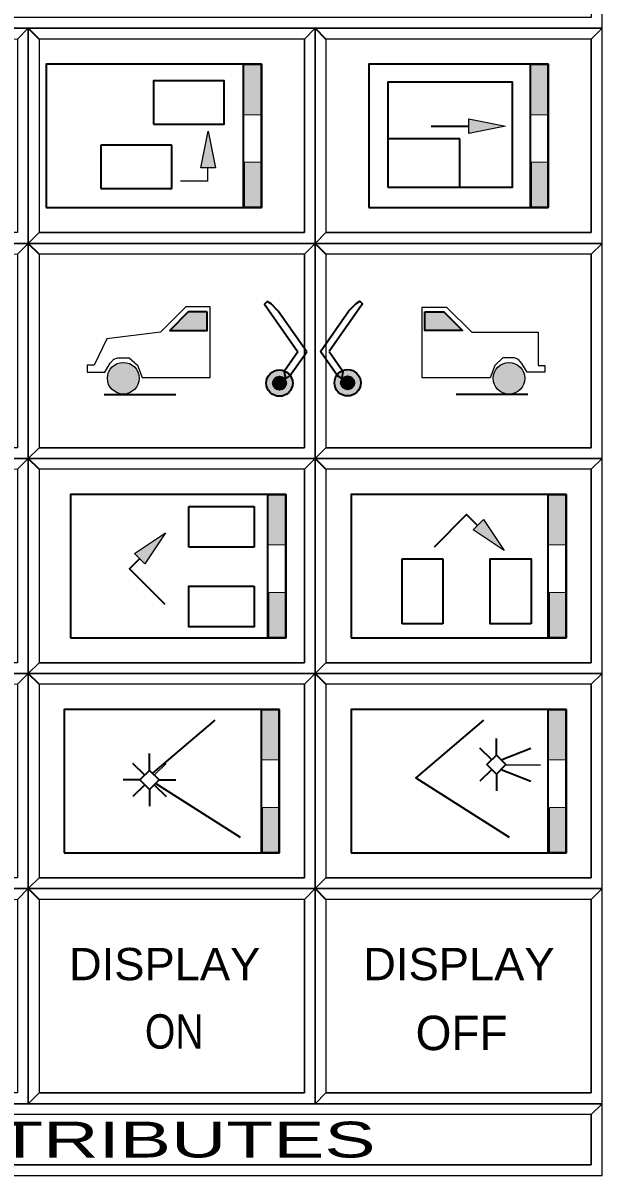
# Model space of a CAD drawing. Extents: x 95906.9 to 95918.9, y 90964.8 to 90972.9.
# Drawn here: x 95917.125 to 95917.932, y 90966.369 to 90967.969 of the extents above; entities that cross this region are included whole.
import ezdxf
from ezdxf.enums import TextEntityAlignment as Align

# ---------------------------------------------------------------- set-up
doc = ezdxf.new("R2010")
doc.units = 0
doc.header["$LTSCALE"] = 0.019
doc.linetypes.add('MEDIUM_DASHED', pattern=[4.5, 3, -1.5])
for name, color, linetype, lineweight in [('1', 7, 'Continuous', 25), ('11', 7, 'Continuous', 25), ('2', 7, 'Continuous', 13), ('21', 7, 'Continuous', 25), ('3', 7, 'Continuous', 25), ('4', 7, 'Continuous', 35), ('6', 7, 'Continuous', 35)]:
    doc.layers.add(name, color=color, linetype=linetype, lineweight=lineweight)

msp = doc.modelspace()

# ---------------------------------------------------------------- hatches: boundary and pattern name
at = {"layer": '6'}
for points in [[(95917.4573, 90967.9117), (95917.4315, 90967.9117), (95917.4315, 90967.8412), (95917.4573, 90967.8412)], [(95917.8573, 90967.9117), (95917.8315, 90967.9117), (95917.8315, 90967.8412), (95917.8573, 90967.8412)], [(95917.7465, 90967.8354), (95917.7977, 90967.8252), (95917.7465, 90967.815)], [(95917.373, 90967.7669), (95917.3832, 90967.8181), (95917.3934, 90967.7669)], [(95917.4339, 90967.7117), (95917.4573, 90967.7117), (95917.4573, 90967.775), (95917.4339, 90967.775)], [(95917.8339, 90967.7117), (95917.8573, 90967.7117), (95917.8573, 90967.775), (95917.8339, 90967.775)], [(95917.3819, 90967.5664), (95917.3554, 90967.5664), (95917.3294, 90967.5404), (95917.3819, 90967.5404)], [(95917.6853, 90967.5662), (95917.7118, 90967.5662), (95917.7378, 90967.5402), (95917.6853, 90967.5402)], [(95917.2426, 90967.4737, 1), (95917.2867, 90967.4737, 1)], [(95917.8246, 90967.4735, 1), (95917.7805, 90967.4735, 1)], [(95917.5009, 90967.4668, 1), (95917.4641, 90967.4668, 1)], [(95917.4917, 90967.4668, 1), (95917.4733, 90967.4668, 1)], [(95917.5591, 90967.4673, 1), (95917.5959, 90967.4673, 1)], [(95917.5683, 90967.4673, 1), (95917.5867, 90967.4673, 1)], [(95917.4912, 90967.3117), (95917.4654, 90967.3117), (95917.4654, 90967.2412), (95917.4912, 90967.2412)], [(95917.8823, 90967.3117), (95917.8565, 90967.3117), (95917.8565, 90967.2412), (95917.8823, 90967.2412)], [(95917.7668, 90967.2768), (95917.7958, 90967.2334), (95917.7524, 90967.2624)], [(95917.2803, 90967.229), (95917.3237, 90967.258), (95917.2947, 90967.2146)], [(95917.4678, 90967.1117), (95917.4912, 90967.1117), (95917.4912, 90967.175), (95917.4678, 90967.175)], [(95917.8589, 90967.1117), (95917.8823, 90967.1117), (95917.8823, 90967.175), (95917.8589, 90967.175)], [(95917.4823, 90967.0117), (95917.4565, 90967.0117), (95917.4565, 90966.9412), (95917.4823, 90966.9412)], [(95917.8823, 90967.0117), (95917.8565, 90967.0117), (95917.8565, 90966.9412), (95917.8823, 90966.9412)], [(95917.4589, 90966.8117), (95917.4823, 90966.8117), (95917.4823, 90966.875), (95917.4589, 90966.875)], [(95917.8589, 90966.8117), (95917.8823, 90966.8117), (95917.8823, 90966.875), (95917.8589, 90966.875)]]:
    msp.add_hatch(color=256, dxfattribs=at).paths.add_polyline_path(points)

# ---------------------------------------------------------------- linework, layer by layer
at = {"layer": '1'}
for points in [[(95916.3323, 90967.9617), (95917.9323, 90967.9617), (95917.9323, 90968.0617), (95916.3323, 90968.0617)], [(95916.7323, 90967.6617), (95917.1323, 90967.6617), (95917.1323, 90967.9617), (95916.7323, 90967.9617)], [(95917.1323, 90967.6617), (95917.5323, 90967.6617), (95917.5323, 90967.9617), (95917.1323, 90967.9617)], [(95917.5323, 90967.6617), (95917.9323, 90967.6617), (95917.9323, 90967.9617), (95917.5323, 90967.9617)], [(95916.7323, 90967.3617), (95917.1323, 90967.3617), (95917.1323, 90967.6617), (95916.7323, 90967.6617)], [(95917.1323, 90967.3617), (95917.5323, 90967.3617), (95917.5323, 90967.6617), (95917.1323, 90967.6617)], [(95917.5323, 90967.3617), (95917.9323, 90967.3617), (95917.9323, 90967.6617), (95917.5323, 90967.6617)], [(95916.7323, 90967.0617), (95917.1323, 90967.0617), (95917.1323, 90967.3617), (95916.7323, 90967.3617)], [(95917.1323, 90967.0617), (95917.5323, 90967.0617), (95917.5323, 90967.3617), (95917.1323, 90967.3617)], [(95917.5323, 90967.0617), (95917.9323, 90967.0617), (95917.9323, 90967.3617), (95917.5323, 90967.3617)], [(95916.7323, 90966.7617), (95917.1323, 90966.7617), (95917.1323, 90967.0617), (95916.7323, 90967.0617)], [(95917.1323, 90966.7617), (95917.5323, 90966.7617), (95917.5323, 90967.0617), (95917.1323, 90967.0617)], [(95917.5323, 90966.7617), (95917.9323, 90966.7617), (95917.9323, 90967.0617), (95917.5323, 90967.0617)], [(95916.7323, 90966.4617), (95917.1323, 90966.4617), (95917.1323, 90966.7617), (95916.7323, 90966.7617)], [(95917.1323, 90966.4617), (95917.5323, 90966.4617), (95917.5323, 90966.7617), (95917.1323, 90966.7617)], [(95917.5323, 90966.4617), (95917.9323, 90966.4617), (95917.9323, 90966.7617), (95917.5323, 90966.7617)], [(95916.3323, 90966.3617), (95917.9323, 90966.3617), (95917.9323, 90966.4617), (95916.3323, 90966.4617)]]:
    msp.add_lwpolyline(points, close=True, dxfattribs=at)
at = {"layer": '11'}
for points in [[(95917.1473, 90967.6767), (95917.5173, 90967.6767), (95917.5173, 90967.9467), (95917.1473, 90967.9467)], [(95917.5473, 90967.6767), (95917.9173, 90967.6767), (95917.9173, 90967.9467), (95917.5473, 90967.9467)], [(95917.1473, 90967.3767), (95917.5173, 90967.3767), (95917.5173, 90967.6467), (95917.1473, 90967.6467)], [(95917.5473, 90967.3767), (95917.9173, 90967.3767), (95917.9173, 90967.6467), (95917.5473, 90967.6467)], [(95917.1473, 90967.0767), (95917.5173, 90967.0767), (95917.5173, 90967.3467), (95917.1473, 90967.3467)], [(95917.5473, 90967.0767), (95917.9173, 90967.0767), (95917.9173, 90967.3467), (95917.5473, 90967.3467)], [(95917.1473, 90966.7767), (95917.5173, 90966.7767), (95917.5173, 90967.0467), (95917.1473, 90967.0467)], [(95917.5473, 90966.7767), (95917.9173, 90966.7767), (95917.9173, 90967.0467), (95917.5473, 90967.0467)], [(95917.1473, 90966.4767), (95917.5173, 90966.4767), (95917.5173, 90966.7467), (95917.1473, 90966.7467)], [(95917.5473, 90966.4767), (95917.9173, 90966.4767), (95917.9173, 90966.7467), (95917.5473, 90966.7467)]]:
    msp.add_lwpolyline(points, close=True, dxfattribs=at)
at = {"layer": '2'}
for points in [[(95916.7323, 90967.9617), (95916.7323, 90967.6617), (95916.7473, 90967.6767), (95916.7473, 90967.9467), (95917.1173, 90967.9467), (95917.1323, 90967.9617)], [(95917.1323, 90967.9617), (95917.1323, 90967.6617), (95917.1473, 90967.6767), (95917.1473, 90967.9467), (95917.5173, 90967.9467), (95917.5323, 90967.9617)], [(95917.5323, 90967.9617), (95917.5323, 90967.6617), (95917.5473, 90967.6767), (95917.5473, 90967.9467), (95917.9173, 90967.9467), (95917.9323, 90967.9617)], [(95916.7323, 90967.6617), (95916.7323, 90967.3617), (95916.7473, 90967.3767), (95916.7473, 90967.6467), (95917.1173, 90967.6467), (95917.1323, 90967.6617)], [(95917.1323, 90967.6617), (95917.1323, 90967.3617), (95917.1473, 90967.3767), (95917.1473, 90967.6467), (95917.5173, 90967.6467), (95917.5323, 90967.6617)], [(95917.5323, 90967.6617), (95917.5323, 90967.3617), (95917.5473, 90967.3767), (95917.5473, 90967.6467), (95917.9173, 90967.6467), (95917.9323, 90967.6617)], [(95916.7323, 90967.3617), (95916.7323, 90967.0617), (95916.7473, 90967.0767), (95916.7473, 90967.3467), (95917.1173, 90967.3467), (95917.1323, 90967.3617)], [(95917.1323, 90967.3617), (95917.1323, 90967.0617), (95917.1473, 90967.0767), (95917.1473, 90967.3467), (95917.5173, 90967.3467), (95917.5323, 90967.3617)], [(95917.5323, 90967.3617), (95917.5323, 90967.0617), (95917.5473, 90967.0767), (95917.5473, 90967.3467), (95917.9173, 90967.3467), (95917.9323, 90967.3617)], [(95916.7323, 90967.0617), (95916.7323, 90966.7617), (95916.7473, 90966.7767), (95916.7473, 90967.0467), (95917.1173, 90967.0467), (95917.1323, 90967.0617)], [(95917.1323, 90967.0617), (95917.1323, 90966.7617), (95917.1473, 90966.7767), (95917.1473, 90967.0467), (95917.5173, 90967.0467), (95917.5323, 90967.0617)], [(95917.5323, 90967.0617), (95917.5323, 90966.7617), (95917.5473, 90966.7767), (95917.5473, 90967.0467), (95917.9173, 90967.0467), (95917.9323, 90967.0617)], [(95916.7323, 90966.7617), (95916.7323, 90966.4617), (95916.7473, 90966.4767), (95916.7473, 90966.7467), (95917.1173, 90966.7467), (95917.1323, 90966.7617)], [(95917.1323, 90966.7617), (95917.1323, 90966.4617), (95917.1473, 90966.4767), (95917.1473, 90966.7467), (95917.5173, 90966.7467), (95917.5323, 90966.7617)], [(95917.5323, 90966.7617), (95917.5323, 90966.4617), (95917.5473, 90966.4767), (95917.5473, 90966.7467), (95917.9173, 90966.7467), (95917.9323, 90966.7617)], [(95916.3323, 90966.4617), (95916.3323, 90966.3617), (95916.3473, 90966.3767), (95916.3473, 90966.4467), (95917.9173, 90966.4467), (95917.9323, 90966.4617)]]:
    msp.add_lwpolyline(points, close=True, dxfattribs=at)
at = {"layer": '21'}
msp.add_lwpolyline([(95916.3473, 90966.3767), (95917.9173, 90966.3767), (95917.9173, 90966.4467), (95916.3473, 90966.4467)], close=True, dxfattribs=at)
at = {"layer": '3'}
for points in [[(95916.3323, 90967.9617), (95917.9323, 90967.9617), (95917.9323, 90968.0617), (95917.9173, 90968.0467), (95917.9173, 90967.9767), (95916.3473, 90967.9767)], [(95916.7323, 90967.6617), (95917.1323, 90967.6617), (95917.1323, 90967.9617), (95917.1173, 90967.9467), (95917.1173, 90967.6767), (95916.7473, 90967.6767)], [(95917.1323, 90967.6617), (95917.5323, 90967.6617), (95917.5323, 90967.9617), (95917.5173, 90967.9467), (95917.5173, 90967.6767), (95917.1473, 90967.6767)], [(95917.5323, 90967.6617), (95917.9323, 90967.6617), (95917.9323, 90967.9617), (95917.9173, 90967.9467), (95917.9173, 90967.6767), (95917.5473, 90967.6767)], [(95916.7323, 90967.3617), (95917.1323, 90967.3617), (95917.1323, 90967.6617), (95917.1173, 90967.6467), (95917.1173, 90967.3767), (95916.7473, 90967.3767)], [(95917.1323, 90967.3617), (95917.5323, 90967.3617), (95917.5323, 90967.6617), (95917.5173, 90967.6467), (95917.5173, 90967.3767), (95917.1473, 90967.3767)], [(95917.5323, 90967.3617), (95917.9323, 90967.3617), (95917.9323, 90967.6617), (95917.9173, 90967.6467), (95917.9173, 90967.3767), (95917.5473, 90967.3767)], [(95916.7323, 90967.0617), (95917.1323, 90967.0617), (95917.1323, 90967.3617), (95917.1173, 90967.3467), (95917.1173, 90967.0767), (95916.7473, 90967.0767)], [(95917.1323, 90967.0617), (95917.5323, 90967.0617), (95917.5323, 90967.3617), (95917.5173, 90967.3467), (95917.5173, 90967.0767), (95917.1473, 90967.0767)], [(95917.5323, 90967.0617), (95917.9323, 90967.0617), (95917.9323, 90967.3617), (95917.9173, 90967.3467), (95917.9173, 90967.0767), (95917.5473, 90967.0767)], [(95916.7323, 90966.7617), (95917.1323, 90966.7617), (95917.1323, 90967.0617), (95917.1173, 90967.0467), (95917.1173, 90966.7767), (95916.7473, 90966.7767)], [(95917.1323, 90966.7617), (95917.5323, 90966.7617), (95917.5323, 90967.0617), (95917.5173, 90967.0467), (95917.5173, 90966.7767), (95917.1473, 90966.7767)], [(95917.5323, 90966.7617), (95917.9323, 90966.7617), (95917.9323, 90967.0617), (95917.9173, 90967.0467), (95917.9173, 90966.7767), (95917.5473, 90966.7767)], [(95916.7323, 90966.4617), (95917.1323, 90966.4617), (95917.1323, 90966.7617), (95917.1173, 90966.7467), (95917.1173, 90966.4767), (95916.7473, 90966.4767)], [(95917.1323, 90966.4617), (95917.5323, 90966.4617), (95917.5323, 90966.7617), (95917.5173, 90966.7467), (95917.5173, 90966.4767), (95917.1473, 90966.4767)], [(95917.5323, 90966.4617), (95917.9323, 90966.4617), (95917.9323, 90966.7617), (95917.9173, 90966.7467), (95917.9173, 90966.4767), (95917.5473, 90966.4767)], [(95916.3323, 90966.3617), (95917.9323, 90966.3617), (95917.9323, 90966.4617), (95917.9173, 90966.4467), (95917.9173, 90966.3767), (95916.3473, 90966.3767)]]:
    msp.add_lwpolyline(points, close=True, dxfattribs=at)
at = {"layer": '4'}
for p, q in [((95917.1473, 90967.9467), (95917.1323, 90967.9617)), ((95917.5473, 90967.9467), (95917.5323, 90967.9617)), ((95917.1473, 90967.6467), (95917.1323, 90967.6617)), ((95917.5473, 90967.6467), (95917.5323, 90967.6617)), ((95917.5473, 90967.6467), (95917.5323, 90967.6617)), ((95917.1473, 90967.3467), (95917.1323, 90967.3617)), ((95917.1473, 90967.3467), (95917.1323, 90967.3617)), ((95917.5473, 90967.3467), (95917.5323, 90967.3617)), ((95917.1473, 90967.0467), (95917.1323, 90967.0617)), ((95917.5473, 90967.0467), (95917.5323, 90967.0617)), ((95917.1473, 90966.7467), (95917.1323, 90966.7617)), ((95917.5473, 90966.7467), (95917.5323, 90966.7617))]:
    msp.add_line(p, q, dxfattribs=at)
at = {"layer": '6'}
for p, q in [((95917.694, 90967.8252), (95917.7465, 90967.8252)), ((95917.3922, 90966.9969), (95917.3053, 90966.923)), ((95917.785, 90966.9479), (95917.785, 90966.9713)), ((95917.3013, 90966.9266), (95917.3013, 90966.95)), ((95917.2881, 90966.9133), (95917.2646, 90966.9133)), ((95917.3145, 90966.9133), (95917.3379, 90966.9133)), ((95917.785, 90966.9214), (95917.785, 90966.898)), ((95917.3013, 90966.9001), (95917.3013, 90966.8767)), ((95917.3103, 90966.9084), (95917.4277, 90966.8337))]:
    msp.add_line(p, q, dxfattribs=at)
at = {"layer": '6', "linetype": 'MEDIUM_DASHED'}
for p, q in [((95917.2382, 90967.451), (95917.3876, 90967.451)), ((95917.829, 90967.4508), (95917.6796, 90967.4508)), ((95917.7784, 90966.9412), (95917.7618, 90966.9578)), ((95917.7916, 90966.9412), (95917.8332, 90966.9578)), ((95917.2947, 90966.9199), (95917.2781, 90966.9365)), ((95917.7784, 90966.928), (95917.7618, 90966.9115)), ((95917.7916, 90966.928), (95917.8332, 90966.9115)), ((95917.2947, 90966.9067), (95917.2781, 90966.8902)), ((95917.3079, 90966.9067), (95917.3245, 90966.8902))]:
    msp.add_line(p, q, dxfattribs=at)
at = {"layer": '6', "linetype": 'MEDIUM_DASHED', "lineweight": 13}
msp.add_line((95917.3079, 90966.9199), (95917.3245, 90966.9365), dxfattribs=at)
at = {"layer": '6', "lineweight": 25}
msp.add_line((95917.7982, 90966.9346), (95917.8466, 90966.9346), dxfattribs=at)
at = {"layer": '6'}
for points in [[(95917.1573, 90967.7117), (95917.4573, 90967.7117), (95917.4573, 90967.9117), (95917.1573, 90967.9117)], [(95917.4573, 90967.7117), (95917.4323, 90967.7117), (95917.4323, 90967.9117), (95917.4573, 90967.9117)], [(95917.6073, 90967.7117), (95917.8573, 90967.7117), (95917.8573, 90967.9117), (95917.6073, 90967.9117)], [(95917.8573, 90967.7117), (95917.8323, 90967.7117), (95917.8323, 90967.9117), (95917.8573, 90967.9117)], [(95917.3068, 90967.8282), (95917.4055, 90967.8282), (95917.4055, 90967.8885), (95917.3068, 90967.8885)], [(95917.6334, 90967.7401), (95917.8072, 90967.7401), (95917.8072, 90967.8867), (95917.6334, 90967.8867)], [(95917.3819, 90967.5664), (95917.3554, 90967.5664), (95917.3294, 90967.5404), (95917.3819, 90967.5404)], [(95917.6853, 90967.5662), (95917.7118, 90967.5662), (95917.7378, 90967.5402), (95917.6853, 90967.5402)], [(95917.1912, 90967.1117), (95917.4912, 90967.1117), (95917.4912, 90967.3117), (95917.1912, 90967.3117)], [(95917.4912, 90967.1117), (95917.4662, 90967.1117), (95917.4662, 90967.3117), (95917.4912, 90967.3117)], [(95917.5823, 90967.1117), (95917.8823, 90967.1117), (95917.8823, 90967.3117), (95917.5823, 90967.3117)], [(95917.8823, 90967.1117), (95917.8573, 90967.1117), (95917.8573, 90967.3117), (95917.8823, 90967.3117)], [(95917.8333, 90967.1309), (95917.7765, 90967.1309), (95917.7765, 90967.2219), (95917.8333, 90967.2219)], [(95917.4472, 90967.1838), (95917.4472, 90967.127), (95917.3562, 90967.127), (95917.3562, 90967.1838)], [(95917.1823, 90966.8117), (95917.4823, 90966.8117), (95917.4823, 90967.0117), (95917.1823, 90967.0117)], [(95917.4823, 90966.8117), (95917.4573, 90966.8117), (95917.4573, 90967.0117), (95917.4823, 90967.0117)], [(95917.5823, 90966.8117), (95917.8823, 90966.8117), (95917.8823, 90967.0117), (95917.5823, 90967.0117)], [(95917.8823, 90966.8117), (95917.8573, 90966.8117), (95917.8573, 90967.0117), (95917.8823, 90967.0117)], [(95917.785, 90966.9214), (95917.7983, 90966.9347), (95917.785, 90966.9479), (95917.7717, 90966.9347)], [(95917.3013, 90966.9001), (95917.3146, 90966.9134), (95917.3013, 90966.9266), (95917.288, 90966.9134)]]:
    msp.add_lwpolyline(points, close=True, dxfattribs=at)
at = {"layer": '6', "lineweight": 13}
for points in [[(95917.4573, 90967.9117), (95917.4315, 90967.9117), (95917.4315, 90967.8412), (95917.4573, 90967.8412)], [(95917.8573, 90967.9117), (95917.8315, 90967.9117), (95917.8315, 90967.8412), (95917.8573, 90967.8412)], [(95917.4339, 90967.7117), (95917.4573, 90967.7117), (95917.4573, 90967.775), (95917.4339, 90967.775)], [(95917.8339, 90967.7117), (95917.8573, 90967.7117), (95917.8573, 90967.775), (95917.8339, 90967.775)], [(95917.4912, 90967.3117), (95917.4654, 90967.3117), (95917.4654, 90967.2412), (95917.4912, 90967.2412)], [(95917.8823, 90967.3117), (95917.8565, 90967.3117), (95917.8565, 90967.2412), (95917.8823, 90967.2412)], [(95917.4678, 90967.1117), (95917.4912, 90967.1117), (95917.4912, 90967.175), (95917.4678, 90967.175)], [(95917.8589, 90967.1117), (95917.8823, 90967.1117), (95917.8823, 90967.175), (95917.8589, 90967.175)], [(95917.4823, 90967.0117), (95917.4565, 90967.0117), (95917.4565, 90966.9412), (95917.4823, 90966.9412)], [(95917.8823, 90967.0117), (95917.8565, 90967.0117), (95917.8565, 90966.9412), (95917.8823, 90966.9412)], [(95917.4589, 90966.8117), (95917.4823, 90966.8117), (95917.4823, 90966.875), (95917.4589, 90966.875)], [(95917.8589, 90966.8117), (95917.8823, 90966.8117), (95917.8823, 90966.875), (95917.8589, 90966.875)]]:
    msp.add_lwpolyline(points, close=True, dxfattribs=at)
at = {"layer": '6', "lineweight": 25}
for points in [[(95917.7465, 90967.8354), (95917.7977, 90967.8252), (95917.7465, 90967.815)], [(95917.373, 90967.7669), (95917.3832, 90967.8181), (95917.3934, 90967.7669)], [(95917.3857, 90967.573), (95917.3517, 90967.573), (95917.3166, 90967.538), (95917.242, 90967.5287), (95917.2239, 90967.4917), (95917.2145, 90967.4917), (95917.2145, 90967.4822), (95917.2391, 90967.4822), (95917.2466, 90967.4945), (95917.2514, 90967.5002), (95917.257, 90967.5021), (95917.2731, 90967.5021), (95917.2845, 90967.4917), (95917.2911, 90967.4746), (95917.3857, 90967.4746)], [(95917.6815, 90967.5728), (95917.7155, 90967.5728), (95917.7506, 90967.5378), (95917.8433, 90967.5379), (95917.8433, 90967.4915), (95917.8527, 90967.4915), (95917.8527, 90967.482), (95917.8281, 90967.482), (95917.8206, 90967.4943), (95917.8158, 90967.5), (95917.8102, 90967.5019), (95917.7941, 90967.5019), (95917.7827, 90967.4915), (95917.7761, 90967.4744), (95917.6815, 90967.4744)], [(95917.7668, 90967.2768), (95917.7958, 90967.2334), (95917.7524, 90967.2624)], [(95917.2803, 90967.229), (95917.3237, 90967.258), (95917.2947, 90967.2146)]]:
    msp.add_lwpolyline(points, close=True, dxfattribs=at)
at = {"layer": '6', "linetype": 'MEDIUM_DASHED'}
for points in [[(95917.2335, 90967.7383), (95917.3322, 90967.7383), (95917.3322, 90967.7986), (95917.2335, 90967.7986)], [(95917.6334, 90967.7401), (95917.7339, 90967.7401), (95917.7339, 90967.8075), (95917.6334, 90967.8075)], [(95917.4472, 90967.2949), (95917.4472, 90967.2381), (95917.3562, 90967.2381), (95917.3562, 90967.2949)], [(95917.7103, 90967.1309), (95917.6535, 90967.1309), (95917.6535, 90967.2219), (95917.7103, 90967.2219)]]:
    msp.add_lwpolyline(points, close=True, dxfattribs=at)
at = {"layer": '6', "lineweight": 25}
msp.add_lwpolyline([(95917.3823, 90967.7661), (95917.3823, 90967.7483), (95917.3444, 90967.7483)], dxfattribs=at)
at = {"layer": '6'}
for points in [[(95917.5205, 90967.5103), (95917.4809, 90967.567), (95917.4707, 90967.5772), (95917.4653, 90967.5805), (95917.4616, 90967.577), (95917.5083, 90967.5103)], [(95917.5395, 90967.5108), (95917.5791, 90967.5675), (95917.5893, 90967.5777), (95917.5947, 90967.581), (95917.5984, 90967.5775), (95917.5518, 90967.5108)], [(95917.5083, 90967.5103), (95917.489, 90967.4828), (95917.4907, 90967.4728), (95917.4967, 90967.4763), (95917.5205, 90967.5103)], [(95917.5518, 90967.5108), (95917.571, 90967.4833), (95917.5693, 90967.4733), (95917.5633, 90967.4768), (95917.5395, 90967.5108)], [(95917.6985, 90967.2385), (95917.7434, 90967.2834), (95917.7584, 90967.2684)], [(95917.3231, 90967.1581), (95917.2734, 90967.2077), (95917.2875, 90967.2218)], [(95917.7672, 90966.9969), (95917.6726, 90966.9165), (95917.8027, 90966.8337)]]:
    msp.add_lwpolyline(points, dxfattribs=at)
at = {"layer": '6', "lineweight": 25}
for centre in [(95917.2646, 90967.4737), (95917.8026, 90967.4735)]:
    msp.add_circle(centre, 0.0221, dxfattribs=at)
at = {"layer": '6'}
for centre, radius in [((95917.4825, 90967.4668), 0.0184), ((95917.4825, 90967.4668), 0.00923), ((95917.5775, 90967.4673), 0.0184), ((95917.5775, 90967.4673), 0.00923)]:
    msp.add_circle(centre, radius, dxfattribs=at)

# ---------------------------------------------------------------- texts
at = {"layer": '21', "width": 1.6}
msp.add_text('    VIEW ATTRIBUTES    ', height=0.04999, dxfattribs=at).set_placement((95917.1322, 90966.3867), align=Align.CENTER)
at = {"layer": '6'}
for s, height, width, p in [('DISPLAY', 0.045, 1.05, (95917.3224, 90966.634)), ('DISPLAY', 0.045, 1.05, (95917.7327, 90966.634)), ('ON', 0.048, 0.85, (95917.3358, 90966.5385))]:
    msp.add_text(s, height=height, dxfattribs=dict(at, width=width)).set_placement(p, align=Align.CENTER)
msp.add_text('OFF', height=0.048, dxfattribs=at).set_placement((95917.7365, 90966.5365), align=Align.CENTER)

doc.saveas('drawing.dxf')
